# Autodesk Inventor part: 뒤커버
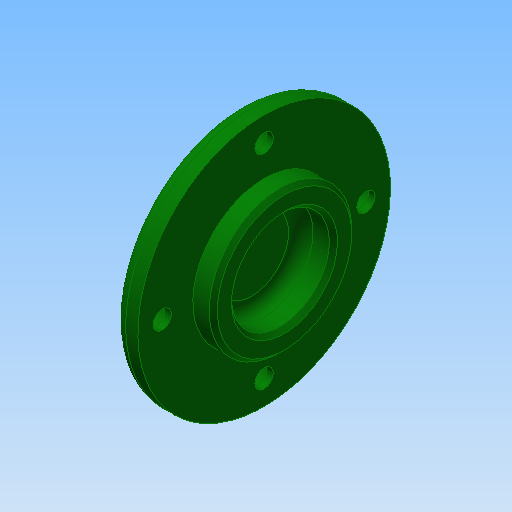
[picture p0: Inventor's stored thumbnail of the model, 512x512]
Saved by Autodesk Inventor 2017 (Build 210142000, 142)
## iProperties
Created: 2015-12
Part Number: 뒤커버
Document SubType Name: Modeling
Designer: mdu
Density: 2.71 g/cm^3
Material: 알루미늄 6061
Appearance: 진녹색
Author: mdu
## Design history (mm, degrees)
sketch "스케치1"
  geometry: L1 (-7, 0)-(7, 0); L2 (-7, 0)-(-7, 15.539); L3 (-7, 15.539)-(-4, 18.5); L4 (-4, 18.5)-(-4, 31); L5 (-4, 31)-(2, 31); L6 (2, 31)-(2, 17.5); L7 (2, 17.5)-(7, 17.5); L8 (7, 17.5)-(7, 0); 2 further points
  constraints: 16 end point, 4 parallel, 2 perpendicular, 1 coincident, 1 horizontal, 1 midpoint
  dimensions: "d0" = 14 distance of L1.start L1.end; "d1" = 62 diameter of L5 L1; "d2" = 35 diameter of L7 L1; "d3" = 37 diameter of L3.end L1; "d4" = 3 distance between parallel lines of L4 L2; "d5" = 6 distance of L4.end L5.end
revolve "회전1" sketch "스케치1" stored, may be unused: angle "d6" = 90 deg
sketch "스케치2" dims "d32" = 50
  geometry: 3 further points
  constraints: 2 vertical alignment, 1 coincident, 2 other
hole "구멍1" sketch "스케치2" at (0, 25) diameter "d8" = 4.5; stored, may be unused: countersink angle "d12" = 90 deg, drill point angle "d14" = 118 deg; dims "d9" = 6, "d10" = 8, "d11" = 4.4, "d13" = 8
hole "구멍2" diameter "d20" = 24; stored, may be unused: countersink angle "d24" = 90 deg, drill point angle "d26" = 0 deg; dims "d18" = 10, "d19" = 10, "d21" = 6, "d22" = 8, "d23" = 4.4, "d25" = 8
fillet "모깎기1" dims "d27" = 3
fillet "모깎기2" dims "d28" = 3
chamfer "모따기1" distance "d29" = 1; stored, may be unused: second distance "d30" = 2, angle "d31" = 45 deg
node "솔리드1"
pattern_circular "원형 패턴1" dims angle "d16" = 360 deg
